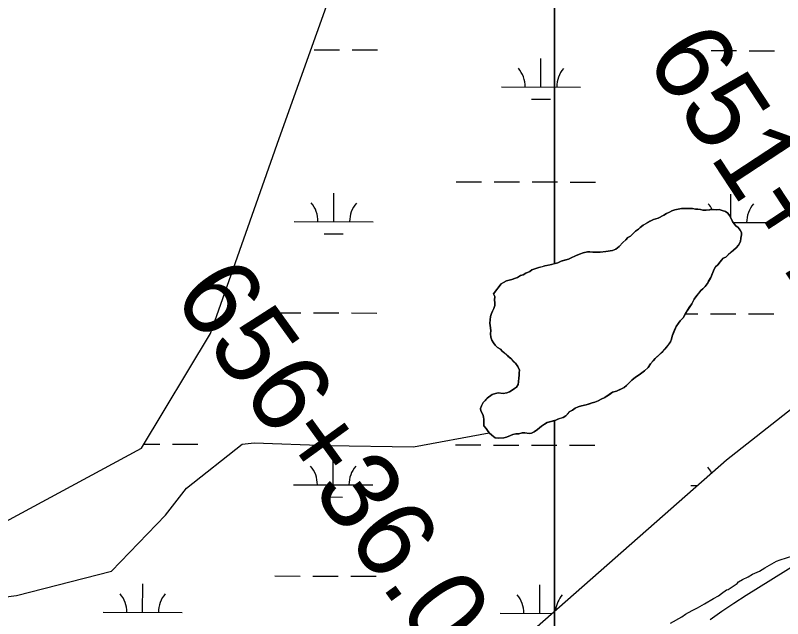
# Model space of a CAD drawing. Extents: x 3177385 to 3215275, y 903885 to 929304.
# Drawn here: x 3190591 to 3191561, y 916041 to 916804 of the extents above; entities that cross this region are included whole.
import ezdxf

# ---------------------------------------------------------------- set-up
doc = ezdxf.new("R2010")
doc.units = 0
for name, color, linetype in [('V-LEVE-TOET', 7, 'Continuous'), ('V-SITE-VEGE', 7, 'Continuous'), ('V-SURV-IDEN', 7, 'Continuous'), ('V-TOPO-SHOR', 7, 'Continuous'), ('V-WETL-SWMP', 7, 'Continuous')]:
    doc.layers.add(name, color=color, linetype=linetype)

msp = doc.modelspace()

# ---------------------------------------------------------------- linework, layer by layer
at = {"layer": 'V-LEVE-TOET'}
for points in [[(3191553.3, 916094.01), (3191553.3, 916094.01), (3191574.12, 916107.23)], [(3191469.6, 916039.73), (3191484.61, 916050.29), (3191499.8, 916060.6), (3191515.16, 916070.64), (3191530.69, 916080.42), (3191546.39, 916089.93), (3191553.3, 916094.01)]]:
    msp.add_lwpolyline(points, dxfattribs=at)
at = {"layer": 'V-SITE-VEGE'}
for points in [[(3191197.62, 916440.46), (3191197.15, 916443.58), (3191197.58, 916448.04), (3191195.78, 916451.6), (3191205.52, 916464.13), (3191208.63, 916465.93), (3191212.19, 916467.74), (3191218.87, 916469.55), (3191225.99, 916472.27), (3191229.99, 916474.52), (3191233.11, 916475.43), (3191236.66, 916477.67), (3191241.56, 916479.93), (3191244.22, 916481.73), (3191248.23, 916483.09), (3191253.12, 916484.9), (3191260.69, 916486.72), (3191269.16, 916488.55), (3191272.99, 916489.72), (3191272.99, 919228.78)], [(3191272.99, 919228.78), (3191272.99, 916489.72), (3191273.61, 916489.91), (3191277.17, 916490.82), (3191281.18, 916492.62), (3191290.53, 916495.35), (3191294.08, 916497.15), (3191299.42, 916499.41), (3191304.32, 916501.66), (3191309.21, 916503.47), (3191314.56, 916504.39), (3191317.68, 916504.41), (3191321.25, 916503.98), (3191330.61, 916504.03), (3191337.74, 916504.96), (3191346.21, 916506.34), (3191350.66, 916508.15), (3191354.66, 916511.29), (3191359.09, 916516.22), (3191363.08, 916519.81), (3191365.74, 916522.5), (3191368.85, 916524.3), (3191371.07, 916526.54), (3191375.51, 916530.58), (3191379.06, 916533.27), (3191381.28, 916535.51), (3191384.83, 916538.21), (3191393.73, 916543.16), (3191398.17, 916545.41), (3191403.96, 916547.23), (3191411.08, 916550.83), (3191414.63, 916553.08), (3191418.19, 916554.88), (3191421.3, 916556.23), (3191424.86, 916557.59), (3191433.33, 916559.42), (3191447.15, 916559.49), (3191451.17, 916558.62), (3191454.29, 916558.64), (3191457.41, 916558.21), (3191460.54, 916557.33), (3191464.55, 916557.35), (3191473.91, 916558.29), (3191477.93, 916557.87), (3191481.05, 916557.89), (3191485.06, 916557.02), (3191489.09, 916555.7), (3191492.22, 916553.49), (3191494.02, 916550.37), (3191496.27, 916546.82), (3191498.07, 916542.82), (3191499.87, 916540.15), (3191502.11, 916537.49), (3191505.25, 916535.27), (3191507.49, 916532.16), (3191509.29, 916529.05), (3191509.31, 916525.93), (3191508.44, 916521.91), (3191508.01, 916517.45), (3191505.36, 916512.98), (3191502.7, 916509.84), (3191492.49, 916500.87), (3191489.39, 916497.73)], [(3191489.39, 916497.73), (3191486.28, 916496.38), (3191484.06, 916494.14), (3191479.19, 916488.31), (3191476.52, 916485.62), (3191474.76, 916482.49), (3191470.35, 916472.21), (3191465.93, 916464.16), (3191463.28, 916460.58), (3191460.62, 916457.89), (3191457.95, 916455.65), (3191452.63, 916449.38), (3191449.54, 916444.9), (3191446.45, 916438.65), (3191440.69, 916430.14), (3191435.39, 916421.2), (3191431.85, 916417.16), (3191429.63, 916414.48), (3191426.53, 916410), (3191421.69, 916397.94), (3191420.82, 916394.37), (3191419.5, 916390.79), (3191414.63, 916384.08), (3191412.41, 916381.39), (3191407.09, 916376.01), (3191399.99, 916369.73), (3191397.78, 916366.6), (3191394.23, 916363.01), (3191391.13, 916358.54), (3191386.69, 916354.05), (3191383.14, 916351.81), (3191380.03, 916349.11), (3191376.48, 916346.86), (3191373.37, 916344.62), (3191370.7, 916342.38), (3191364.05, 916335.65), (3191360.94, 916332.96), (3191351.16, 916328.45), (3191346.26, 916327.08), (3191336.48, 916320.34), (3191332.03, 916318.54), (3191328.03, 916316.29), (3191324.03, 916314.48), (3191320.46, 916313.57), (3191312.9, 916311.3), (3191307.11, 916309.93), (3191302.66, 916308.58), (3191299.1, 916306.77), (3191295.54, 916304.52), (3191292.43, 916302.72), (3191287.11, 916297.34), (3191284, 916295.1), (3191277.32, 916293.28), (3191273.76, 916291.48), (3191272.99, 916291.27), (3191272.99, 915915.1)], [(3191272.99, 915915.1), (3191272.99, 916291.27), (3191263.52, 916288.75), (3191260.41, 916286.95), (3191256.41, 916284.25), (3191251.53, 916280.21), (3191247.08, 916277.07), (3191243.97, 916275.27), (3191240.85, 916274.81), (3191235.5, 916275.67), (3191231.93, 916275.65), (3191227.92, 916274.74), (3191223.91, 916274.72), (3191220.34, 916273.81), (3191212.34, 916270.2), (3191208.78, 916269.29), (3191202.09, 916269.25), (3191198.07, 916269.68), (3191193.6, 916272.77), (3191190.46, 916275.88), (3191188.21, 916278.54), (3191186.42, 916281.21), (3191183.72, 916284.76), (3191183.68, 916292.79), (3191183.22, 916295.91), (3191182.31, 916299.02), (3191179.61, 916303.47), (3191179.59, 916306.59), (3191180.47, 916309.72), (3191182.68, 916314.19), (3191188, 916319.56), (3191194.22, 916324.06), (3191198.22, 916325.42), (3191201.79, 916326.33), (3191208.03, 916325.47), (3191212.49, 916326.38), (3191216.05, 916327.74), (3191219.6, 916329.54), (3191222.27, 916331.79), (3191224.93, 916333.58), (3191227.15, 916336.71), (3191227.58, 916340.29), (3191228, 916345.19), (3191228.43, 916348.32), (3191228.41, 916351.44), (3191228.84, 916355.01), (3191226.58, 916359.45), (3191223.44, 916363.9), (3191217.61, 916369.66), (3191206.86, 916378.97), (3191204.62, 916381.64), (3191201.04, 916383.85), (3191197.9, 916386.5), (3191195.66, 916389.61), (3191193.86, 916392.73), (3191192.5, 916396.73), (3191192.03, 916400.74), (3191192.45, 916405.2), (3191191.07, 916414.56), (3191191.91, 916423.04), (3191193.23, 916426.61), (3191194.55, 916429.74), (3191196.32, 916432.87), (3191197.64, 916436.89), (3191197.62, 916440.46)], [(3191419.55, 916035.05), (3191433.68, 916043.23), (3191438.39, 916046.63), (3191447.14, 916051.4), (3191453.88, 916054.81), (3191462.63, 916059.58), (3191474.07, 916066.39), (3191480.13, 916069.8), (3191484.16, 916072.52), (3191490.22, 916077.28), (3191492.24, 916077.96), (3191503.67, 916085.45), (3191505.69, 916087.49), (3191510.4, 916090.21), (3191517.81, 916093.63), (3191523.19, 916097.03), (3191531.95, 916101.13), (3191538.68, 916105.21), (3191553.49, 916113.39), (3191558.2, 916115.44), (3191574.38, 916120.25)]]:
    msp.add_lwpolyline(points, dxfattribs=at)
at = {"layer": 'V-TOPO-SHOR'}
for points in [[(3191351.16, 916328.45), (3191356.94, 916331.16), (3191360.94, 916332.96), (3191364.05, 916335.65), (3191368.04, 916339.69), (3191370.7, 916342.38), (3191373.37, 916344.62), (3191376.48, 916346.86), (3191380.03, 916349.11), (3191383.14, 916351.81), (3191386.69, 916354.05), (3191391.13, 916358.54), (3191394.23, 916363.01), (3191397.77, 916366.6), (3191399.99, 916369.73), (3191403.98, 916373.32), (3191407.09, 916376.01), (3191409.75, 916378.7), (3191412.41, 916381.39), (3191414.63, 916384.08), (3191416.84, 916387.21), (3191419.5, 916390.79), (3191420.82, 916394.37), (3191421.69, 916397.94), (3191423.45, 916402.41), (3191424.77, 916405.53), (3191426.53, 916410), (3191429.63, 916414.48), (3191431.85, 916417.16), (3191435.39, 916421.2), (3191438.04, 916425.67), (3191440.69, 916430.14), (3191443.35, 916434.17), (3191446.45, 916438.65), (3191449.54, 916444.9), (3191452.63, 916449.38), (3191455.74, 916452.96), (3191457.95, 916455.65), (3191460.62, 916457.89), (3191463.28, 916460.58), (3191465.93, 916464.16), (3191467.7, 916467.3), (3191470.35, 916472.21), (3191471.67, 916475.34), (3191472.99, 916478.47), (3191474.76, 916482.49), (3191476.52, 916485.62), (3191479.18, 916488.31), (3191481.84, 916491.45), (3191484.06, 916494.14), (3191486.28, 916496.38), (3191489.39, 916497.73), (3191492.49, 916500.87), (3191496.49, 916504.46), (3191499.15, 916506.7), (3191502.7, 916509.84), (3191505.36, 916512.98), (3191508.01, 916517.45), (3191508.44, 916521.91), (3191509.31, 916525.93), (3191509.29, 916529.05), (3191507.49, 916532.16), (3191505.25, 916535.27), (3191502.11, 916537.49), (3191499.87, 916540.15), (3191498.07, 916542.82), (3191496.27, 916546.82), (3191494.02, 916550.37), (3191492.22, 916553.49), (3191489.08, 916555.7), (3191485.06, 916557.02), (3191481.05, 916557.89), (3191477.93, 916557.87), (3191473.91, 916558.29), (3191469.01, 916557.82), (3191464.55, 916557.35), (3191460.54, 916557.33), (3191457.41, 916558.21), (3191454.29, 916558.64), (3191451.17, 916558.62), (3191447.15, 916559.49), (3191441.8, 916559.46), (3191437.78, 916559.44), (3191433.33, 916559.42), (3191429.32, 916558.51), (3191424.86, 916557.59), (3191421.3, 916556.23), (3191418.19, 916554.88), (3191414.63, 916553.08), (3191411.08, 916550.83), (3191407.52, 916549.03), (3191403.96, 916547.23), (3191398.17, 916545.41), (3191393.73, 916543.16), (3191389.72, 916540.91), (3191384.83, 916538.21), (3191381.28, 916535.51), (3191379.06, 916533.27), (3191375.51, 916530.58), (3191371.07, 916526.54), (3191368.85, 916524.3)], [(3191368.85, 916524.3), (3191365.74, 916522.5), (3191363.08, 916519.81), (3191359.09, 916516.22), (3191354.65, 916511.29), (3191350.66, 916508.15), (3191346.21, 916506.34), (3191343.09, 916505.88), (3191337.74, 916504.96), (3191334.62, 916504.5), (3191330.61, 916504.03), (3191325.26, 916504), (3191321.25, 916503.98), (3191317.68, 916504.41), (3191314.56, 916504.39), (3191309.21, 916503.47), (3191304.32, 916501.66), (3191299.42, 916499.41), (3191294.08, 916497.15), (3191290.53, 916495.35), (3191285.63, 916493.98), (3191281.18, 916492.62), (3191277.17, 916490.82), (3191273.61, 916489.91), (3191269.16, 916488.55), (3191265.15, 916487.63), (3191260.69, 916486.72), (3191257.13, 916485.81), (3191253.12, 916484.9), (3191248.23, 916483.09), (3191244.22, 916481.73), (3191241.56, 916479.93), (3191236.66, 916477.67), (3191233.11, 916475.43), (3191229.99, 916474.52), (3191225.99, 916472.27), (3191222.43, 916470.91), (3191218.87, 916469.55), (3191215.75, 916468.65), (3191212.19, 916467.74), (3191208.63, 916465.93), (3191205.52, 916464.13), (3191195.78, 916451.6)], [(3191195.78, 916451.6), (3191197.58, 916448.04), (3191197.15, 916443.58), (3191197.62, 916440.46), (3191197.64, 916436.89), (3191196.32, 916432.87), (3191194.55, 916429.74), (3191193.23, 916426.61), (3191191.91, 916423.04), (3191191.49, 916418.58), (3191191.07, 916414.56), (3191191.53, 916411.44), (3191191.99, 916408.32), (3191192.45, 916405.2), (3191192.03, 916400.74), (3191192.5, 916396.73), (3191193.86, 916392.73), (3191195.66, 916389.61), (3191197.9, 916386.5), (3191201.04, 916383.85), (3191204.62, 916381.64), (3191206.86, 916378.97), (3191209.99, 916376.31), (3191214.03, 916372.77), (3191217.61, 916369.66), (3191220.3, 916367), (3191223.44, 916363.9), (3191226.58, 916359.45), (3191228.84, 916355.01), (3191228.41, 916351.44), (3191228.42, 916348.32), (3191228, 916345.19), (3191227.58, 916340.29), (3191227.15, 916336.71), (3191224.93, 916333.58), (3191222.27, 916331.79), (3191219.6, 916329.54), (3191216.05, 916327.74), (3191212.49, 916326.38), (3191208.03, 916325.47), (3191201.79, 916326.33), (3191198.22, 916325.42), (3191194.22, 916324.06), (3191191.11, 916321.81), (3191188, 916319.56), (3191184.89, 916316.43), (3191182.68, 916314.19), (3191180.47, 916309.72), (3191179.59, 916306.59), (3191179.61, 916303.47), (3191182.31, 916299.02), (3191183.22, 916295.91), (3191183.68, 916292.79), (3191183.7, 916288.33), (3191183.72, 916284.76), (3191186.42, 916281.21), (3191188.21, 916278.54), (3191190.46, 916275.88), (3191193.6, 916272.77), (3191198.07, 916269.68), (3191202.09, 916269.25), (3191205.65, 916269.27), (3191208.78, 916269.29), (3191212.34, 916270.2), (3191216.34, 916272), (3191220.34, 916273.81), (3191223.91, 916274.72), (3191227.92, 916274.74), (3191231.93, 916275.65), (3191235.5, 916275.67), (3191240.85, 916274.81), (3191243.97, 916275.27), (3191247.08, 916277.07), (3191251.53, 916280.21), (3191256.41, 916284.25), (3191260.41, 916286.95), (3191263.52, 916288.75), (3191267.08, 916289.66), (3191270.2, 916290.57), (3191273.76, 916291.48), (3191277.32, 916293.28), (3191280.43, 916294.19), (3191284, 916295.1), (3191287.11, 916297.34), (3191289.32, 916299.59), (3191292.43, 916302.72), (3191295.54, 916304.52), (3191299.1, 916306.77), (3191302.66, 916308.58), (3191307.11, 916309.93), (3191312.9, 916311.3), (3191317.35, 916312.66), (3191320.46, 916313.57), (3191324.03, 916314.48), (3191328.03, 916316.29), (3191332.03, 916318.54), (3191336.48, 916320.34), (3191339.15, 916322.14), (3191342.26, 916324.39), (3191346.26, 916327.08), (3191351.16, 916328.45)], [(3190516.84, 916060.59), (3190592.94, 916070.32), (3190712.76, 916101.09), (3190781.09, 916171.69), (3190807.64, 916206.02), (3190877.92, 916261.4), (3190893.14, 916263.35), (3190986.4, 916259.79), (3191094.89, 916258.18), (3191190.46, 916275.88)]]:
    msp.add_lwpolyline(points, dxfattribs=at)
at = {"layer": 'V-WETL-SWMP'}
for p, q in [((3190969.02, 916760.1), (3191001.02, 916760.03)), ((3191017.02, 916759.99), (3191049.02, 916759.92)), ((3191422.93, 916759.05), (3191454.93, 916758.97)), ((3191470.93, 916758.93), (3191502.93, 916758.86)), ((3191518.93, 916758.82), (3191550.93, 916758.75)), ((3191255.75, 916713), (3191255.84, 916749)), ((3191205.75, 916713.12), (3191305.75, 916712.89)), ((3191243.72, 916697.6), (3191267.72, 916697.55)), ((3191148.63, 916593.18), (3191180.63, 916593.11)), ((3191196.63, 916593.07), (3191228.63, 916593)), ((3191244.63, 916592.96), (3191276.63, 916592.88)), ((3191292.63, 916592.85), (3191324.63, 916592.77)), ((3190993.92, 916542.8), (3190994.01, 916578.8)), ((3191495.84, 916547.49), (3191495.91, 916577.63)), ((3190943.92, 916542.92), (3191043.92, 916542.68)), ((3191498.87, 916541.63), (3191545.83, 916541.52)), ((3190981.89, 916527.4), (3191005.89, 916527.34)), ((3190920.25, 916427.54), (3190952.25, 916427.47)), ((3190968.25, 916427.43), (3191000.25, 916427.35)), ((3191016.25, 916427.32), (3191048.25, 916427.24)), ((3191438.44, 916426.33), (3191454.15, 916426.3)), ((3191470.15, 916426.26), (3191502.15, 916426.19)), ((3191518.15, 916426.15), (3191550.15, 916426.07)), ((3191204.98, 916380.45), (3191205.62, 916380.45)), ((3190753.94, 916261.43), (3190773.95, 916261.38)), ((3190789.95, 916261.34), (3190821.95, 916261.27)), ((3191147.86, 916260.51), (3191179.86, 916260.43)), ((3191195.86, 916260.4), (3191227.86, 916260.32)), ((3191243.86, 916260.29), (3191275.86, 916260.21)), ((3191291.86, 916260.17), (3191323.86, 916260.1)), ((3190993.15, 916210.13), (3190993.23, 916246.13)), ((3190943.15, 916210.24), (3191043.15, 916210.01)), ((3191445.05, 916209.07), (3191453.03, 916209.06)), ((3190981.11, 916194.72), (3191005.11, 916194.67)), ((3190919.47, 916094.87), (3190951.47, 916094.79)), ((3190967.47, 916094.75), (3190999.47, 916094.68)), ((3191015.47, 916094.64), (3191047.47, 916094.57)), ((3190752.3, 916048.82), (3190752.38, 916084.82)), ((3191254.21, 916047.66), (3191254.29, 916083.66)), ((3190702.3, 916048.94), (3190802.3, 916048.71)), ((3191204.21, 916047.77), (3191269.68, 916047.62))]:
    msp.add_line(p, q, dxfattribs=at)
for points in [[(3187662.95, 916111.29), (3187822.42, 915951.73), (3187967.39, 915835.69), (3188083.37, 915777.66), (3188315.33, 915690.63), (3188764.75, 915574.58), (3189069.2, 915545.57), (3189417.14, 915502.06), (3189750.58, 915502.06), (3190185.5, 915516.56), (3190591.43, 915690.63), (3191127.83, 915922.72), (3191490.27, 916241.85), (3192099.16, 916720.53), (3192273.13, 916764.05), (3192389.11, 916836.58), (3192679.06, 917126.69), (3192809.54, 917286.25), (3192969.01, 917460.32), (3193229.96, 917648.9), (3193403.93, 917808.46), (3193519.91, 917968.02), (3194390.37, 918496.3)], [(3190562.43, 916154.81), (3190750.9, 916256.35), (3190837.89, 916401.41), (3190924.87, 916648), (3190997.36, 916851.08), (3191055.35, 917039.66), (3191084.34, 917199.22), (3191156.83, 917286.25), (3191301.8, 917358.78), (3191417.78, 917431.31), (3191432.28, 917532.85), (3191446.78, 917648.89), (3191533.76, 917779.45), (3191794.72, 917808.46), (3191794.72, 917880.99), (3191751.22, 917953.51)], [(3191403.98, 916373.32), (3191407.09, 916376.01), (3191412.41, 916381.39), (3191414.63, 916384.08), (3191416.84, 916387.21), (3191419.5, 916390.79), (3191420.82, 916394.37), (3191421.69, 916397.94), (3191423.45, 916402.41), (3191424.77, 916405.53), (3191426.53, 916410), (3191429.63, 916414.48), (3191431.85, 916417.16), (3191435.39, 916421.2), (3191440.7, 916430.14), (3191443.35, 916434.17), (3191446.45, 916438.65), (3191449.54, 916444.9), (3191452.63, 916449.38), (3191455.74, 916452.96), (3191457.95, 916455.65), (3191460.62, 916457.89), (3191463.28, 916460.58), (3191465.93, 916464.16), (3191467.7, 916467.3), (3191470.35, 916472.21), (3191472.99, 916478.47), (3191474.76, 916482.49), (3191476.52, 916485.62), (3191479.18, 916488.31), (3191481.84, 916491.45), (3191484.06, 916494.14), (3191486.28, 916496.38), (3191489.39, 916497.73), (3191492.5, 916500.87), (3191496.49, 916504.46), (3191499.15, 916506.7), (3191502.7, 916509.84), (3191505.36, 916512.98), (3191508.02, 916517.45), (3191508.44, 916521.91), (3191509.31, 916525.93), (3191509.29, 916529.05), (3191507.49, 916532.16), (3191505.25, 916535.27), (3191502.11, 916537.49), (3191499.87, 916540.15), (3191498.07, 916542.81), (3191496.27, 916546.82), (3191494.02, 916550.37), (3191492.22, 916553.49), (3191489.09, 916555.7), (3191485.07, 916557.02), (3191481.05, 916557.89), (3191477.93, 916557.87), (3191473.91, 916558.29), (3191469.01, 916557.82), (3191464.55, 916557.35), (3191460.54, 916557.33), (3191457.41, 916558.21), (3191454.29, 916558.64), (3191451.17, 916558.62), (3191447.15, 916559.49), (3191433.33, 916559.42), (3191429.32, 916558.51), (3191424.86, 916557.59), (3191421.3, 916556.23), (3191418.19, 916554.88), (3191414.63, 916553.08), (3191411.08, 916550.83), (3191403.96, 916547.23), (3191398.17, 916545.41), (3191393.73, 916543.16), (3191389.72, 916540.91), (3191384.83, 916538.21), (3191381.28, 916535.51), (3191379.06, 916533.27), (3191375.51, 916530.58), (3191371.07, 916526.54), (3191368.85, 916524.3), (3191365.74, 916522.5), (3191363.08, 916519.81), (3191359.09, 916516.22), (3191354.65, 916511.29), (3191350.66, 916508.15), (3191346.21, 916506.34), (3191343.09, 916505.88), (3191337.74, 916504.96), (3191334.62, 916504.5), (3191330.61, 916504.03), (3191321.25, 916503.98), (3191317.68, 916504.41), (3191314.56, 916504.39), (3191309.21, 916503.47), (3191304.32, 916501.66), (3191299.42, 916499.41), (3191294.08, 916497.15), (3191290.53, 916495.35), (3191285.63, 916493.98), (3191281.18, 916492.62), (3191277.17, 916490.82)], [(3191277.17, 916490.82), (3191273.61, 916489.91), (3191269.16, 916488.55), (3191265.15, 916487.63), (3191260.69, 916486.72), (3191257.13, 916485.81), (3191253.12, 916484.9), (3191248.23, 916483.09), (3191244.22, 916481.73), (3191241.56, 916479.93), (3191236.66, 916477.67), (3191233.11, 916475.43), (3191229.99, 916474.52), (3191225.99, 916472.27), (3191218.87, 916469.55), (3191215.75, 916468.65), (3191212.19, 916467.74), (3191208.63, 916465.93), (3191205.52, 916464.13), (3191195.78, 916451.6), (3191197.58, 916448.04), (3191197.16, 916443.58), (3191197.62, 916440.46), (3191197.64, 916436.89), (3191196.32, 916432.87)], [(3191196.32, 916432.87), (3191194.55, 916429.74), (3191193.23, 916426.61), (3191191.91, 916423.04), (3191191.49, 916418.58), (3191191.07, 916414.56), (3191192.45, 916405.2), (3191192.03, 916400.74), (3191192.5, 916396.73), (3191193.86, 916392.73), (3191195.66, 916389.61), (3191197.9, 916386.5), (3191201.04, 916383.85), (3191204.62, 916381.63), (3191206.86, 916378.97), (3191209.99, 916376.31), (3191214.03, 916372.77), (3191217.61, 916369.66), (3191223.44, 916363.9), (3191226.58, 916359.45), (3191228.84, 916355.01), (3191228.41, 916351.44), (3191228.42, 916348.32), (3191228, 916345.19), (3191227.58, 916340.29), (3191227.15, 916336.72), (3191224.93, 916333.58), (3191222.27, 916331.78), (3191219.61, 916329.54), (3191216.05, 916327.74), (3191212.49, 916326.38), (3191208.03, 916325.47), (3191201.79, 916326.33), (3191198.22, 916325.42), (3191194.22, 916324.06), (3191188, 916319.57), (3191182.67, 916314.19), (3191180.47, 916309.72), (3191179.59, 916306.59), (3191179.61, 916303.47), (3191182.31, 916299.02), (3191183.22, 916295.91), (3191183.68, 916292.79), (3191183.72, 916284.76), (3191186.42, 916281.21), (3191188.21, 916278.54), (3191190.46, 916275.88), (3191193.59, 916272.77), (3191198.07, 916269.68), (3191202.09, 916269.25), (3191208.77, 916269.29), (3191212.34, 916270.2), (3191220.34, 916273.81), (3191223.91, 916274.72), (3191227.92, 916274.74), (3191231.93, 916275.65), (3191235.5, 916275.67), (3191240.85, 916274.81), (3191243.97, 916275.27), (3191247.08, 916277.07), (3191251.52, 916280.21), (3191256.41, 916284.25), (3191260.41, 916286.95), (3191263.52, 916288.75), (3191267.08, 916289.66), (3191270.2, 916290.57), (3191273.76, 916291.48), (3191277.32, 916293.28), (3191280.44, 916294.19), (3191284, 916295.1), (3191287.11, 916297.34), (3191292.43, 916302.72), (3191295.54, 916304.52), (3191299.1, 916306.77), (3191302.66, 916308.57), (3191307.11, 916309.94), (3191312.9, 916311.3), (3191317.35, 916312.66), (3191320.47, 916313.57), (3191324.03, 916314.48), (3191328.03, 916316.29), (3191332.03, 916318.54), (3191336.48, 916320.35), (3191339.15, 916322.14), (3191342.26, 916324.39), (3191346.26, 916327.09), (3191351.16, 916328.45), (3191356.94, 916331.16), (3191360.94, 916332.96), (3191364.05, 916335.65), (3191370.7, 916342.38), (3191373.37, 916344.62), (3191376.48, 916346.87), (3191380.03, 916349.11), (3191383.14, 916351.81), (3191386.69, 916354.05), (3191391.13, 916358.54), (3191394.23, 916363.01), (3191397.78, 916366.6), (3191399.99, 916369.73), (3191403.98, 916373.32)]]:
    msp.add_lwpolyline(points, dxfattribs=at)
for centre, start, end in [((3191200.51, 916713.61), 359.09484, 40.6385), ((3191311, 916713.35), 139.09484, 180.6385), ((3190938.68, 916543.4), 359.09484, 40.6385), ((3191049.17, 916543.15), 139.09484, 180.6385), ((3191440.59, 916542.24), 26.78264, 40.6385), ((3191551.07, 916541.98), 139.09484, 180.6385), ((3190937.91, 916210.73), 359.09484, 40.6385), ((3191048.39, 916210.47), 139.09484, 180.6385), ((3191439.81, 916209.56), 26.38043, 40.6385), ((3190697.06, 916049.43), 359.09484, 40.6385), ((3190807.54, 916049.17), 139.09484, 180.6385), ((3191198.96, 916048.26), 359.09484, 40.6385), ((3191309.45, 916048), 139.09484, 173.84718)]:
    msp.add_arc(centre, 35.25, start, end, dxfattribs=at)

# ---------------------------------------------------------------- texts
at = {"layer": 'V-SURV-IDEN'}
for s, rotation, p in [('651+72.1', 303.29972, (3191386.53, 916749.18)), ('656+36.0', 305.83583, (3190788.88, 916448.19))]:
    msp.add_text(s, height=100, rotation=rotation, dxfattribs=at).set_placement(p)

doc.saveas('drawing.dxf')
